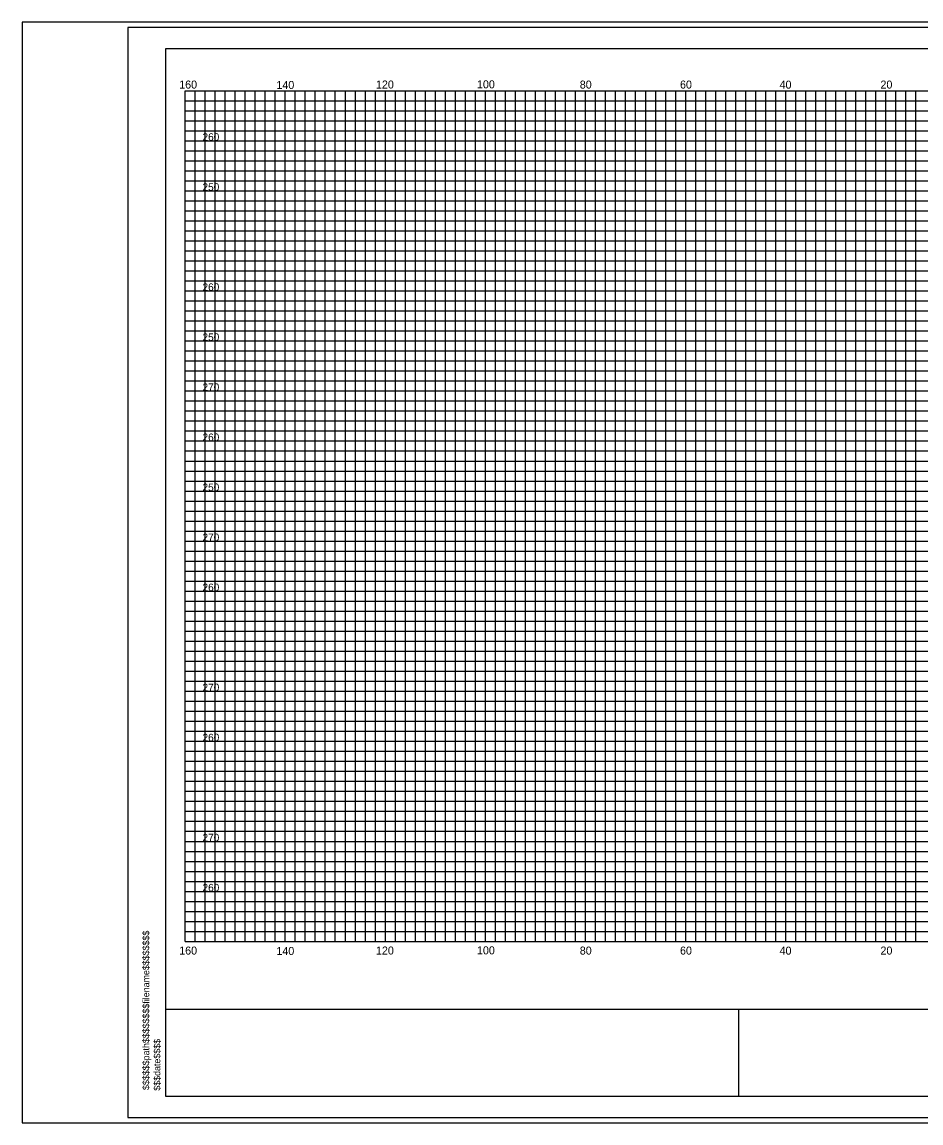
# Model space of a CAD drawing. Extents: x 967 to 1326, y 964 to 1744.
# Drawn here: x 967.4 to 1147, y 963.7 to 1183.7 of the extents above; entities that cross this region are included whole.
import ezdxf

# ---------------------------------------------------------------- set-up
doc = ezdxf.new("R2010")
doc.units = 0
for name, color, linetype in [('Default', 7, 'Continuous'), ('RD_SHT_Bndy', 7, 'Continuous'), ('RD_SHT_IplotShp', 7, 'Continuous'), ('RD_SHT_MjGrid', 7, 'Continuous'), ('RD_SHT_MnGrid', 7, 'Continuous'), ('RD_SHT_TX', 7, 'Continuous'), ('RD_Sketch1', 7, 'Continuous')]:
    doc.layers.add(name, color=color, linetype=linetype)

msp = doc.modelspace()

# ---------------------------------------------------------------- linework, layer by layer
at = {"layer": 'RD_SHT_Bndy'}
for p, q in [((996.11, 968.98), (996.11, 1178.46)), ((996.11, 1178.46), (1323.89, 1178.46)), ((996.11, 986.49), (1323.89, 986.49)), ((1110.59, 968.98), (1110.59, 986.56)), ((1323.89, 968.98), (996.11, 968.98))]:
    msp.add_line(p, q, dxfattribs=at)
at = {"layer": 'RD_SHT_IplotShp'}
for points in [[(967.41, 963.72), (1326.28, 963.72), (1326.28, 1183.72), (967.41, 1183.72)], [(988.52, 964.84), (1326.28, 964.84), (1326.28, 1182.6), (988.52, 1182.6)]]:
    msp.add_lwpolyline(points, close=True, dxfattribs=at)
at = {"layer": 'RD_SHT_MjGrid'}
for p, q in [((1000, 1170), (1320, 1170)), ((1000, 1000), (1000, 1170)), ((1010, 1000), (1010, 1170)), ((1020, 1000), (1020, 1170)), ((1030, 1000), (1030, 1170)), ((1040, 1000), (1040, 1170)), ((1050, 1000), (1050, 1170)), ((1060, 1000), (1060, 1170)), ((1070, 1000), (1070, 1170)), ((1080, 1000), (1080, 1170)), ((1090, 1000), (1090, 1170)), ((1100, 1000), (1100, 1170)), ((1110, 1000), (1110, 1170)), ((1120, 1000), (1120, 1170)), ((1130, 1000), (1130, 1170)), ((1140, 1000), (1140, 1170)), ((1000, 1160), (1320, 1160)), ((1000, 1150), (1320, 1150)), ((1000, 1140), (1320, 1140)), ((1000, 1130), (1320, 1130)), ((1000, 1120), (1320, 1120)), ((1000, 1110), (1320, 1110)), ((1000, 1100), (1320, 1100)), ((1000, 1090), (1320, 1090)), ((1000, 1080), (1320, 1080)), ((1000, 1070), (1320, 1070)), ((1000, 1060), (1320, 1060)), ((1000, 1050), (1320, 1050)), ((1000, 1040), (1320, 1040)), ((1000, 1030), (1320, 1030)), ((1000, 1020), (1320, 1020)), ((1000, 1010), (1320, 1010)), ((1000, 1000), (1320, 1000))]:
    msp.add_line(p, q, dxfattribs=at)
at = {"layer": 'RD_SHT_MnGrid'}
for p, q in [((1002, 1000), (1002, 1170)), ((1004, 1000), (1004, 1170)), ((1006, 1000), (1006, 1170)), ((1008, 1000), (1008, 1170)), ((1012, 1000), (1012, 1170)), ((1014, 1000), (1014, 1170)), ((1016, 1000), (1016, 1170)), ((1018, 1000), (1018, 1170)), ((1022, 1000), (1022, 1170)), ((1024, 1000), (1024, 1170)), ((1026, 1000), (1026, 1170)), ((1028, 1000), (1028, 1170)), ((1032, 1000), (1032, 1170)), ((1034, 1000), (1034, 1170)), ((1036, 1000), (1036, 1170)), ((1038, 1000), (1038, 1170)), ((1042, 1000), (1042, 1170)), ((1044, 1000), (1044, 1170)), ((1046, 1000), (1046, 1170)), ((1048, 1000), (1048, 1170)), ((1052, 1000), (1052, 1170)), ((1054, 1000), (1054, 1170)), ((1056, 1000), (1056, 1170)), ((1058, 1000), (1058, 1170)), ((1062, 1000), (1062, 1170)), ((1064, 1000), (1064, 1170)), ((1066, 1000), (1066, 1170)), ((1068, 1000), (1068, 1170)), ((1072, 1000), (1072, 1170)), ((1074, 1000), (1074, 1170)), ((1076, 1000), (1076, 1170)), ((1078, 1000), (1078, 1170)), ((1082, 1000), (1082, 1170)), ((1084, 1000), (1084, 1170)), ((1086, 1000), (1086, 1170)), ((1088, 1000), (1088, 1170)), ((1092, 1000), (1092, 1170)), ((1094, 1000), (1094, 1170)), ((1096, 1000), (1096, 1170)), ((1098, 1000), (1098, 1170)), ((1102, 1000), (1102, 1170)), ((1104, 1000), (1104, 1170)), ((1106, 1000), (1106, 1170)), ((1108, 1000), (1108, 1170)), ((1112, 1000), (1112, 1170)), ((1114, 1000), (1114, 1170)), ((1116, 1000), (1116, 1170)), ((1118, 1000), (1118, 1170)), ((1122, 1000), (1122, 1170)), ((1124, 1000), (1124, 1170)), ((1126, 1000), (1126, 1170)), ((1128, 1000), (1128, 1170)), ((1132, 1000), (1132, 1170)), ((1134, 1000), (1134, 1170)), ((1136, 1000), (1136, 1170)), ((1138, 1000), (1138, 1170)), ((1142, 1000), (1142, 1170)), ((1144, 1000), (1144, 1170)), ((1146, 1000), (1146, 1170)), ((1000, 1168), (1320, 1168)), ((1000, 1166), (1320, 1166)), ((1000, 1164), (1320, 1164)), ((1000, 1162), (1320, 1162)), ((1000, 1158), (1320, 1158)), ((1000, 1156), (1320, 1156)), ((1000, 1154), (1320, 1154)), ((1000, 1152), (1320, 1152)), ((1000, 1148), (1320, 1148)), ((1000, 1146), (1320, 1146)), ((1000, 1144), (1320, 1144)), ((1000, 1142), (1320, 1142)), ((1000, 1138), (1320, 1138)), ((1000, 1136), (1320, 1136)), ((1000, 1134), (1320, 1134)), ((1000, 1132), (1320, 1132)), ((1000, 1128), (1320, 1128)), ((1000, 1126), (1320, 1126)), ((1000, 1124), (1320, 1124)), ((1000, 1122), (1320, 1122)), ((1000, 1118), (1320, 1118)), ((1000, 1116), (1320, 1116)), ((1000, 1114), (1320, 1114)), ((1000, 1112), (1320, 1112)), ((1000, 1108), (1320, 1108)), ((1000, 1106), (1320, 1106)), ((1000, 1104), (1320, 1104)), ((1000, 1102), (1320, 1102)), ((1000, 1098), (1320, 1098)), ((1000, 1096), (1320, 1096)), ((1000, 1094), (1320, 1094)), ((1000, 1092), (1320, 1092)), ((1000, 1088), (1320, 1088)), ((1000, 1086), (1320, 1086)), ((1000, 1084), (1320, 1084)), ((1000, 1082), (1320, 1082)), ((1000, 1078), (1320, 1078)), ((1000, 1076), (1320, 1076)), ((1000, 1074), (1320, 1074)), ((1000, 1072), (1320, 1072)), ((1000, 1068), (1320, 1068)), ((1000, 1066), (1320, 1066)), ((1000, 1064), (1320, 1064)), ((1000, 1062), (1320, 1062)), ((1000, 1058), (1320, 1058)), ((1000, 1056), (1320, 1056)), ((1000, 1054), (1320, 1054)), ((1000, 1052), (1320, 1052)), ((1000, 1048), (1320, 1048)), ((1000, 1046), (1320, 1046)), ((1000, 1044), (1320, 1044)), ((1000, 1042), (1320, 1042)), ((1000, 1038), (1320, 1038)), ((1000, 1036), (1320, 1036)), ((1000, 1034), (1320, 1034)), ((1000, 1032), (1320, 1032)), ((1000, 1028), (1320, 1028)), ((1000, 1026), (1320, 1026)), ((1000, 1024), (1320, 1024)), ((1000, 1022), (1320, 1022)), ((1000, 1018), (1320, 1018)), ((1000, 1016), (1320, 1016)), ((1000, 1014), (1320, 1014)), ((1000, 1012), (1320, 1012)), ((1000, 1008), (1320, 1008)), ((1000, 1006), (1320, 1006)), ((1000, 1004), (1320, 1004)), ((1000, 1002), (1320, 1002))]:
    msp.add_line(p, q, dxfattribs=at)
at = {"layer": 'RD_Sketch1'}
msp.add_lwpolyline([(967.41, 963.72), (1326.28, 963.72), (1326.28, 1183.72), (967.41, 1183.72)], close=True, dxfattribs=at)

# ---------------------------------------------------------------- texts
at = {"layer": 'Default'}
for s, p in [('260', (1003.47, 1160)), ('250', (1003.47, 1150)), ('260', (1003.47, 1130)), ('250', (1003.47, 1120)), ('270', (1003.47, 1110)), ('260', (1003.47, 1100)), ('250', (1003.47, 1090)), ('270', (1003.47, 1080)), ('260', (1003.47, 1070)), ('270', (1003.47, 1050)), ('260', (1003.47, 1040)), ('270', (1003.47, 1020)), ('260', (1003.47, 1010))]:
    msp.add_text(s, height=1.5, dxfattribs=at).set_placement(p)
for s, p in [('$$$$$$path$$$$$$$$filename$$$$$$$$', (992.83, 970.31)), ('$$$date$$$$', (995.04, 970.17))]:
    msp.add_text(s, height=1.3258, rotation=90, dxfattribs=at).set_placement(p)
at = {"layer": 'RD_SHT_TX'}
for s, p in [('160', (998.81, 1170.42)), ('140', (1018.23, 1170.34)), ('120', (1038.12, 1170.43)), ('100', (1058.3, 1170.47)), ('80', (1078.84, 1170.42)), ('60', (1098.86, 1170.42)), ('40', (1118.75, 1170.41)), ('20', (1138.91, 1170.42)), ('160', (998.81, 997.37)), ('140', (1018.23, 997.29)), ('120', (1038.12, 997.38)), ('100', (1058.3, 997.42)), ('80', (1078.84, 997.37)), ('60', (1098.86, 997.37)), ('40', (1118.75, 997.36)), ('20', (1138.91, 997.37))]:
    msp.add_text(s, height=1.6, dxfattribs=at).set_placement(p)

doc.saveas('drawing.dxf')
